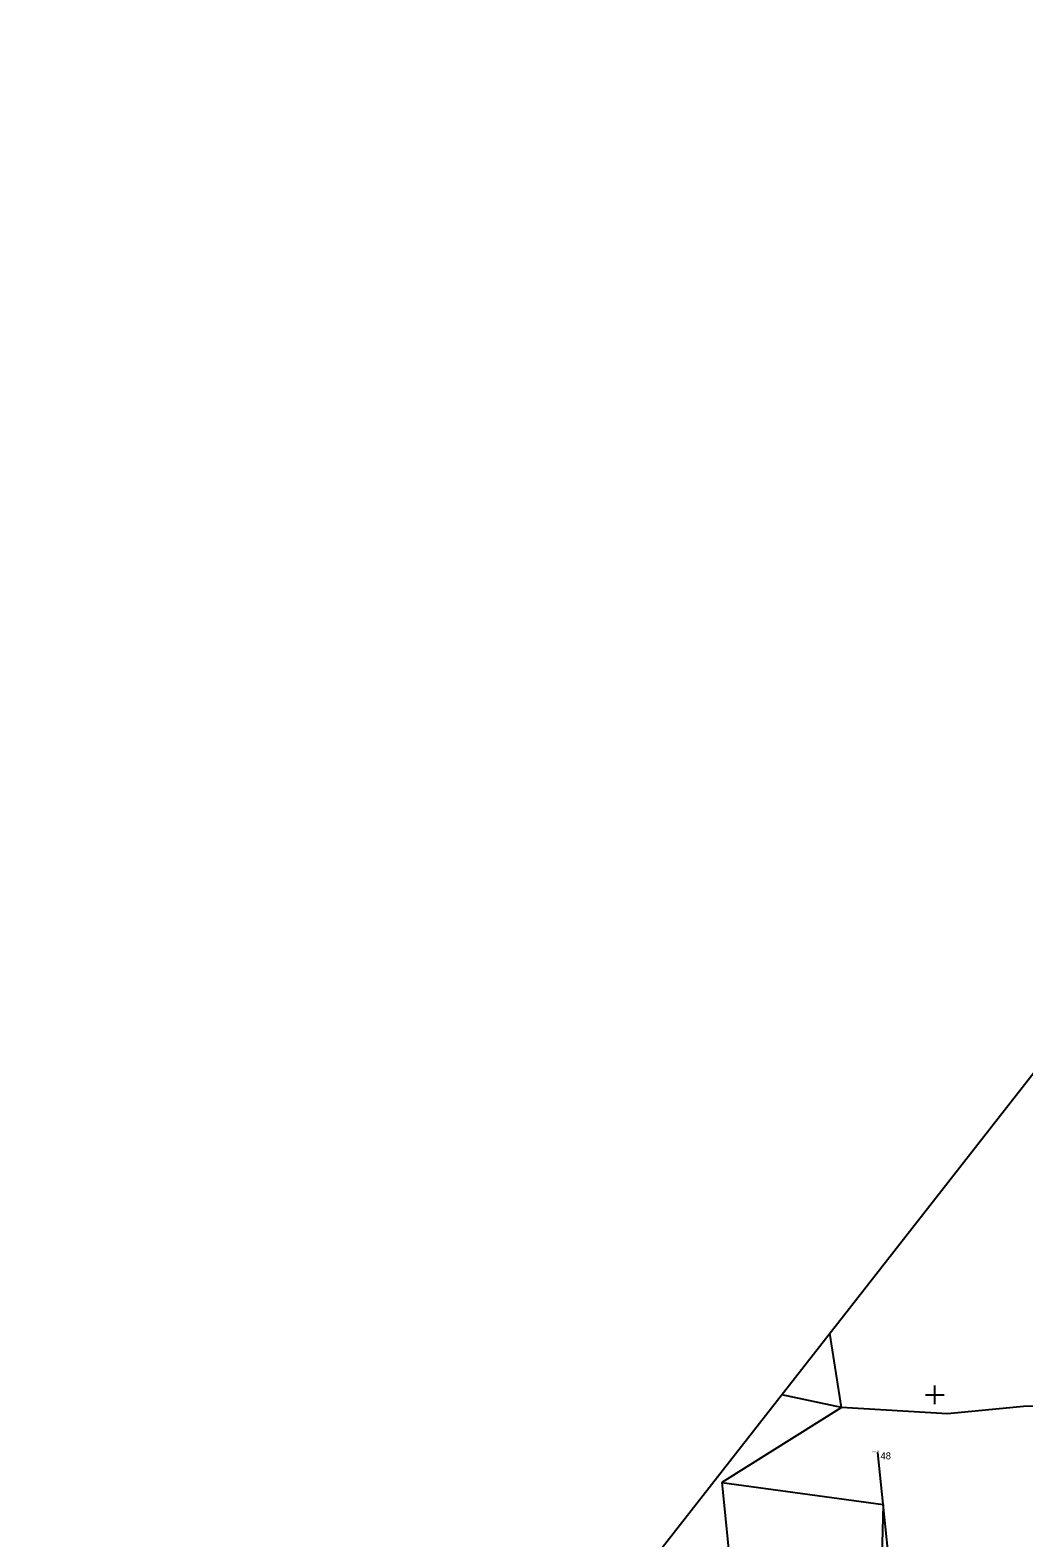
# Model space of a CAD drawing. Extents: x -594197 to -593885, y -1138044 to -1137704.
# Drawn here: x -594196.5 to -594090.5, y -1137865.2 to -1137704.4 of the extents above; entities that cross this region are included whole.
import ezdxf

# ---------------------------------------------------------------- set-up
doc = ezdxf.new("R2010")
doc.units = 0
for name, color, linetype in [('Katastrální mapa', 7, 'Continuous'), ('Podrobný bod', 7, 'Continuous'), ('Podrobný bod výška', 7, 'Continuous'), ('Podrobný bod číslo', 7, 'Continuous'), ('Ram mapoveho listu', 7, 'Continuous'), ('Rozhraní ploch', 7, 'Continuous'), ('Čtvercová síť', 7, 'Continuous')]:
    doc.layers.add(name, color=color, linetype=linetype)

msp = doc.modelspace()

# ---------------------------------------------------------------- linework, layer by layer
at = {"layer": 'Katastrální mapa'}
for q in [(-594116.34, -1137849.99), (-594122.72, -1137859.34)]:
    msp.add_line((-594109.98, -1137851.34), q, dxfattribs=at)
for points in [[(-594109.98, -1137851.34), (-594111.2, -1137843.43)], [(-593966.04, -1137847.69), (-593975.47, -1137848.8), (-593975.47, -1137844.32), (-594010, -1137848.42), (-594038.47, -1137851.11), (-594090.55, -1137851.25), (-594098.65, -1137852.01), (-594109.98, -1137851.34)], [(-594122.72, -1137859.34), (-594120.63, -1137880.3), (-594122.39, -1137886.83), (-594125.63, -1137893.36), (-594128.54, -1137908.17), (-594123.89, -1137962.84)], [(-594122.72, -1137859.34), (-594105.5, -1137861.68), (-594106.87, -1137914.54), (-594112.21, -1137946.48), (-594118.04, -1137962.87), (-594123.89, -1137962.84)]]:
    msp.add_lwpolyline(points, dxfattribs=at)
at = {"layer": 'Podrobný bod'}
msp.add_line((-594106.08, -1137856.13), (-594106.08, -1137856.13), dxfattribs=at)
at = {"layer": 'Ram mapoveho listu'}
msp.add_line((-594002.41, -1137704.42), (-594196.55, -1137952.49), dxfattribs=at)
at = {"layer": 'Rozhraní ploch'}
msp.add_lwpolyline([(-594098.37, -1138025.23), (-594097.42, -1138020.88), (-594096.44, -1138015.16), (-594095.71, -1138009.9), (-594095.18, -1138005.26), (-594094.63, -1137998.75), (-594094.37, -1137992.38), (-594094.32, -1137983.2), (-594094.65, -1137973.95), (-594095.11, -1137967.54), (-594095.75, -1137960.98), (-594097.41, -1137943.93), (-594098.5, -1137932.77), (-594099.57, -1137922.21), (-594100.64, -1137910.93), (-594102.1, -1137896.65), (-594103.58, -1137881.21), (-594104.68, -1137869.94), (-594106.08, -1137856.13)], dxfattribs=at)
at = {"layer": 'Čtvercová síť'}
for p, q in [((-594100, -1137851), (-594100, -1137849)), ((-594101, -1137850), (-594099, -1137850))]:
    msp.add_line(p, q, dxfattribs=at)

# ---------------------------------------------------------------- texts
at = {"layer": 'Podrobný bod výška'}
msp.add_text('285.34 ', height=0.188, dxfattribs=at).set_placement((-594106.71, -1137856.13))
at = {"layer": 'Podrobný bod číslo'}
msp.add_text(' 48', height=0.75, dxfattribs=at).set_placement((-594106.08, -1137856.88))

doc.saveas('drawing.dxf')
